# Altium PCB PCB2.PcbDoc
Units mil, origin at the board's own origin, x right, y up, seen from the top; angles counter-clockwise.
Board outline 6000 x 8455 mil, 2 copper layers (Top Layer, Bottom Layer); 0 components, 0 nets, 0 pads, 0 vias.
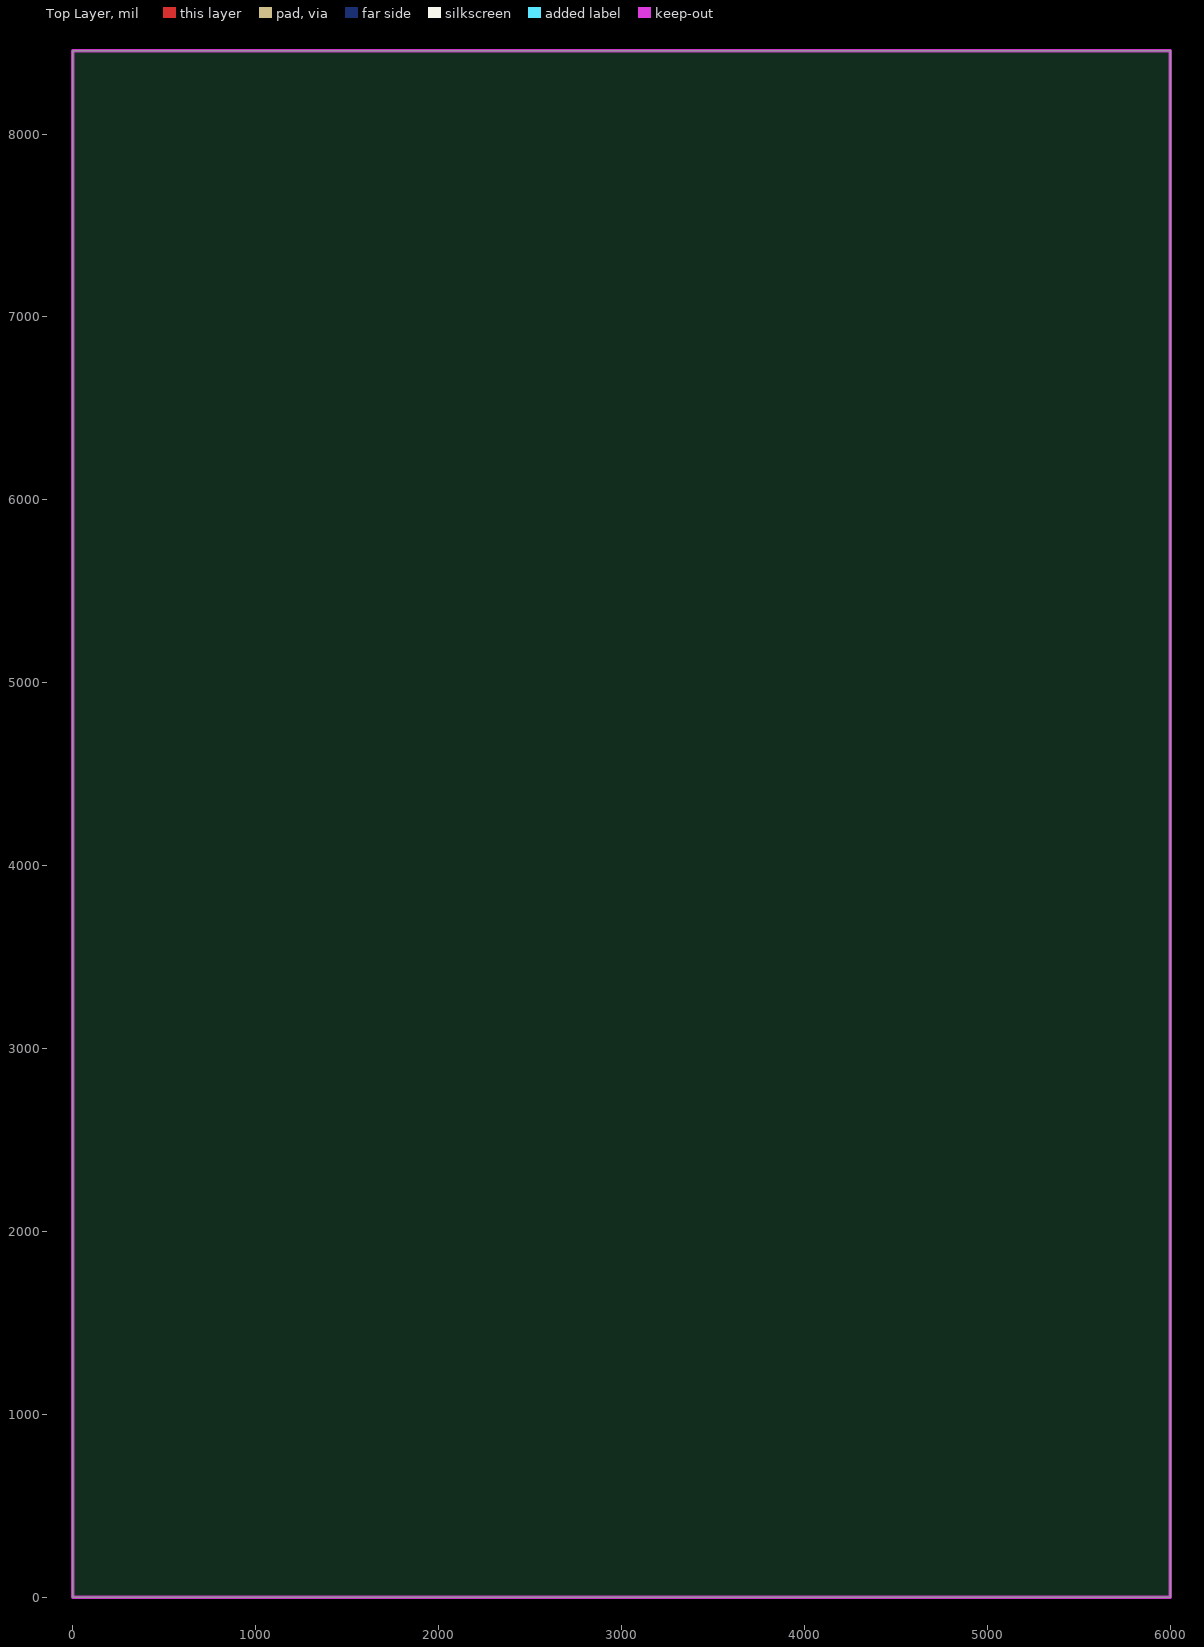
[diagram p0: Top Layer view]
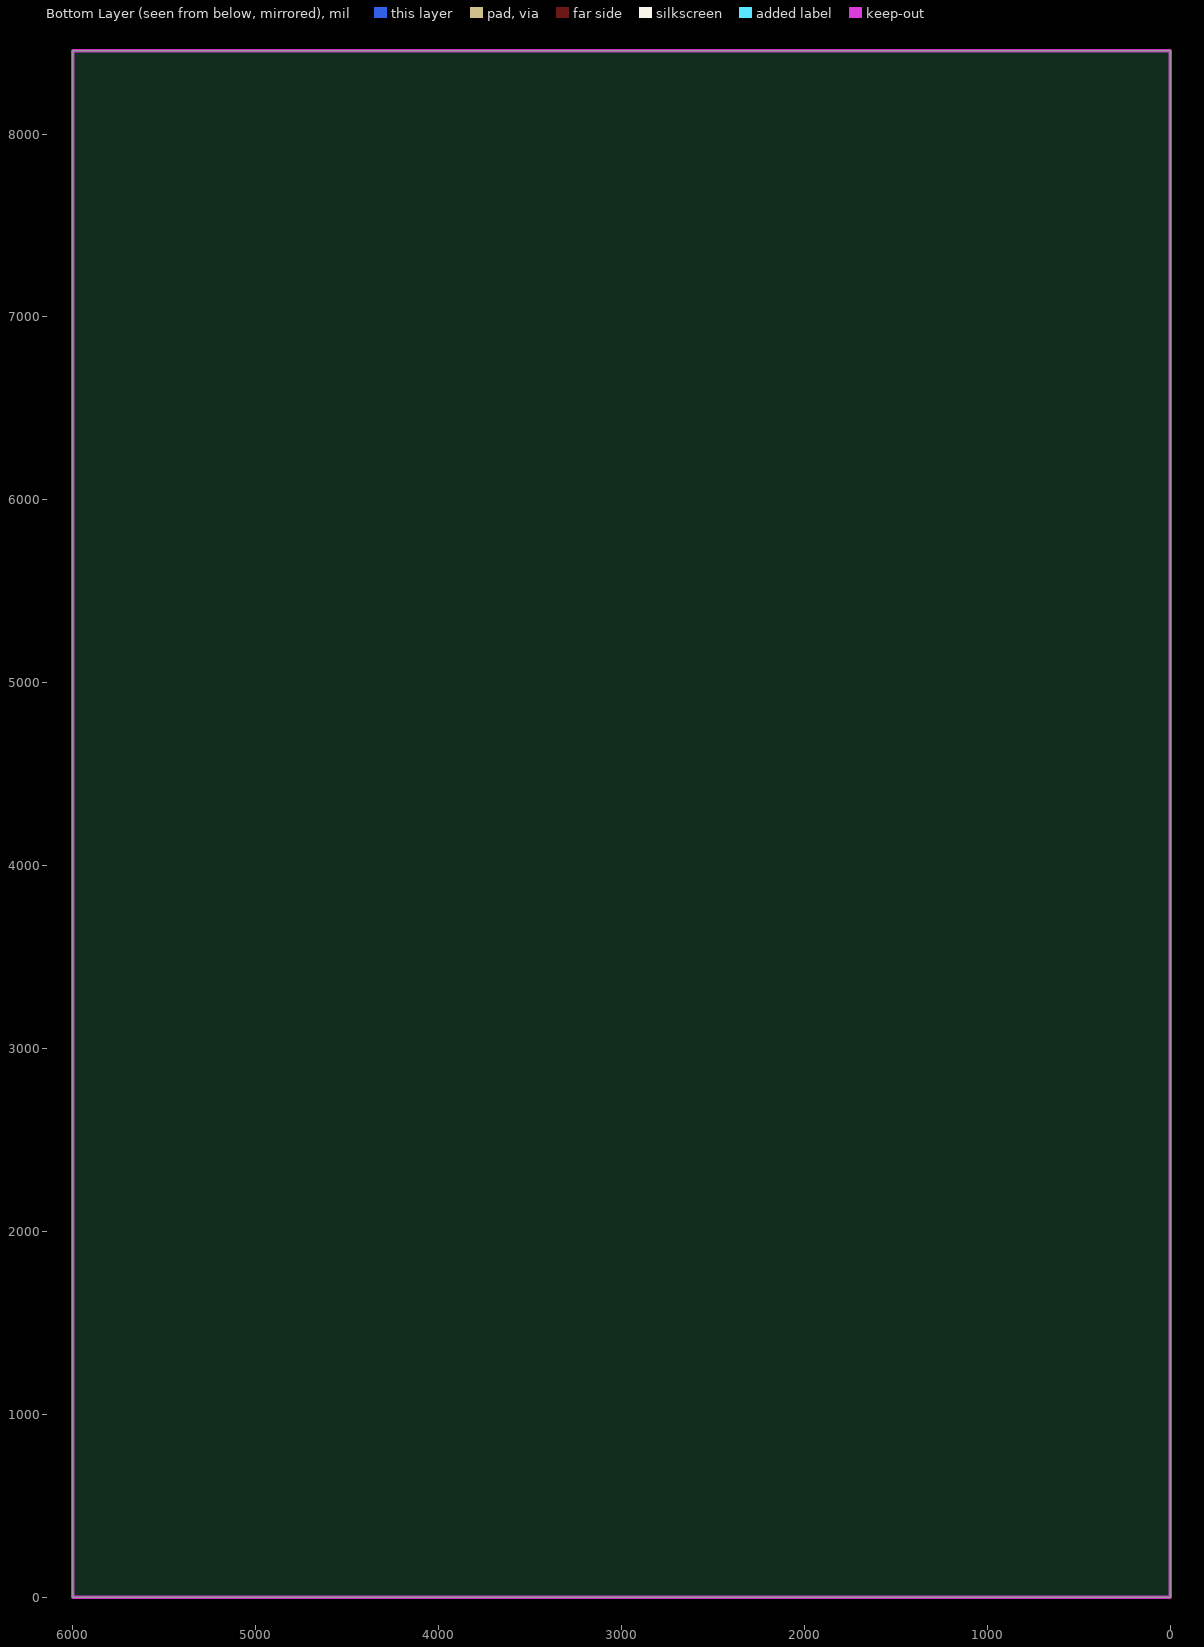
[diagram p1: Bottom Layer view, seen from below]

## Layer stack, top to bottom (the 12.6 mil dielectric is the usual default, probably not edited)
Top Solder: solder mask 0.4, Solder Resist, Dk 3.5
Top Layer: signal copper 1.4
Dielectric 1: dielectric 12.6, FR-4, Dk 4.8
Bottom Layer: signal copper 1.4
Bottom Solder: solder mask 0.4, Solder Resist, Dk 3.5

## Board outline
0,0 6000,0 6000,8455 2970,8455 0,8455

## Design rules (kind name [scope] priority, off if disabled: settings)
Clearance [All] p1: gap=10
PolygonConnect [All] p1: connectstyle=Relief reliefconductorwidth=10 reliefentries=4 polygonreliefangle="90 Angle" airgapwidth=10
RoutingVias [All] p1: holewidth=28 width=50 viastyle="Through Hole" minholewidth=28 minwidth=50 maxholewidth=28 maxwidth=50
SolderMaskExpansion [All] p1: expansion=4
Width [All] p1: maxlimit=10 minlimit=10 preferedwidth=10
30 further rules are at their usual default settings.

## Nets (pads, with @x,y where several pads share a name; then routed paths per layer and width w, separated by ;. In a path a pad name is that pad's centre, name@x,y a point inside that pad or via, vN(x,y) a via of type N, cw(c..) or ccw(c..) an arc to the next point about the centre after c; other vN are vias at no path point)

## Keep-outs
Keep-Out Layer:
  the board outline again, w20

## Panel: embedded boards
"..\Students\5\kenzo\PCBALTIUM\PCB1.PcbDoc" at 0,5700, 1 rows x 1 columns, spacing 3149.61 x 3149.61, rotation 0
"..\Students\4\ELECH402_Labo6 AS-Ni\Labo6 AS-Ni\PCB_Project\PCB1.PcbDoc" at 2850,2850, 1 rows x 1 columns, spacing 3149.61 x 3149.61, rotation 0
"..\Students\3\Project_JLM_H402\PCB1.PcbDoc" at 0,2850, 1 rows x 1 columns, spacing 3149.61 x 3149.61, rotation 0
"..\Students\1\PCB_Project\PCB1.PcbDoc" at 2850,0, 1 rows x 1 columns, spacing 3149.61 x 3149.61, rotation 0
"..\Students\2\PCB_Project\PCB1.PcbDoc" at 0,0, 1 rows x 1 columns, spacing 3149.61 x 3149.61, rotation 0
